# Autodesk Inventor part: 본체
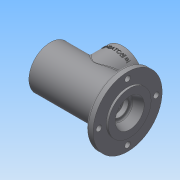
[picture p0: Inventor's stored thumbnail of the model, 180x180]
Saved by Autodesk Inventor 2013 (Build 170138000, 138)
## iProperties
Created: 2016-08
Part Number: 본체
Material: 일반
Document SubType Name: Modeling
Designer: Administrator
Density: 1 g/cm^3
Author: Administrator
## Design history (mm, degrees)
sketch "스케치1"
  geometry: L1 (-57.5, 0)-(57.5, 0); L2 (-57.5, 31)-(44.5, 31); L3 (44.5, 31)-(44.5, 50); L4 (44.5, 50)-(54.5, 50); L5 (57.5, 0)-(57.5, 21); L6 (57.5, 31)-(54.5, 31); L7 (54.5, 31)-(54.5, 50); L8 (-57.5, 20)-(-48.5, 20); L9 (-48.5, 20)-(-48.5, 24); L10 (-48.5, 24)-(-45.5, 24); L11 (-45.5, 24)-(-45.5, 20); L12 (-45.5, 20)-(-36.5, 20); L13 (-36.5, 20)-(-36.5, 17.5); L14 (-36.5, 17.5)-(-33.25, 17.5); L15 (-33.25, 17.5)-(-33.25, 18.5); L16 (-33.25, 18.5)-(-31.5, 18.5); L17 (-31.5, 18.5)-(-31.5, 17.5); L18 (-31.5, 17.5)-(-20.5, 17.5); L19 (17.5, 17.5)-(28.5, 17.5); L20 (28.5, 17.5)-(28.5, 16.5); L21 (28.5, 16.5)-(33.5, 16.5); L22 (33.5, 16.5)-(33.5, 10); L23 (33.5, 10)-(36.2, 10); L24 (36.2, 10)-(36.2, 12.5); L25 (36.2, 12.5)-(43.5, 12.5); L26 (43.5, 12.5)-(43.5, 16); L27 (43.5, 16)-(57.5, 21); L28 (-57.5, 31)-(-57.5, 20); L29 (57.5, 21)-(57.5, 31); L30 (-57.5, 20)-(-57.5, 0); L31 (17.5, 17.5)-(17.5, 24); L32 (17.5, 24)-(-20.5, 24); L33 (-20.5, 24)-(-20.5, 17.5); 2 further points
  constraints: 66 end point, 9 parallel, 9 perpendicular, 2 coincident, 1 horizontal, 1 midpoint
  dimensions: "d0" = 115 distance of L1.start L1.end; "d1" = 31 distance of L1.start L2.start; "d2" = 102 distance of L2.start L2.end; "d4" = 10 distance of L3.end L4.end; "d5" = 31 distance of L1.end L6.start; "d6" = 3 distance of L6.start L6.end; "d7" = 100 diameter of L4 L1; "d13" = 9 distance of L8.start L8.end; "d14" = 3 distance of L9.end L10.end; "d15" = 9 distance of L11.end L12.end; "d18" = 21 distance of L1.end L5.end; "d19" = 14 horizontal distance of L1.end L26.end; "d20" = 16 vertical distance of L1.end L26.end; "d21" = 10 horizontal distance of L22.end L25.end; "d22" = 2.7 distance between parallel lines of L24 L22; "d24" = 5 distance of L20.end L21.end; "d25" = 60 distance of L17.end L19.end; "d27" = 1.75 distance between parallel lines of L17 L15; "d28" = 40 diameter of L8 L1; "d29" = 48 diameter of L10 L1; "d30" = 40 diameter of L12 L1; "d31" = 35 diameter of L14 L1; "d32" = 37 diameter of L16 L1; "d33" = 35 diameter of L18 L1; "d34" = 35 diameter of L19 L1; "d35" = 33 diameter of L21 L1; "d36" = 20 diameter of L23 L1; "d37" = 25 diameter of L25 L1; "d38" = 1 distance of L16.end L17.end; "d92" = 38 distance of L31.end L32.end; "d93" = 11 distance from line of L32.end L17; "d97" = 24 distance from line of point (0, 0) L32
revolve "회전1" sketch "스케치1" stored, may be unused: angle "d41" = 90 deg
feature "스레드1" dims "d42" = 10, "d43" = 0
fillet "모깎기2" dims "d45" = 3
chamfer "모따기1" distance "d46" = 0.7; stored, may be unused: second distance "d47" = 2, angle "d48" = 30 deg
fillet "모깎기3" dims "d49" = 3
fillet "모깎기4" dims "d50" = 0.3
sketch "스케치3"
  geometry: C1 r 31 at (0, 0) reference; C2 r 50 at (0, 0) reference; A1 r 41.5 centre (0, 0) between (0, 41.5) and (-41.5, 0); 2 further points
  constraints: 4 point on circle, 2 horizontal alignment, 2 vertical alignment, 1 centre point, 1 coincident
  dimensions: "d51" = 83 diameter of A1
hole "구멍1" sketch "스케치3" at (0, 41.5), (-41.5, 0), (0, -41.5), (41.5, 0) diameter "d52" = 8; stored, may be unused: countersink angle "d56" = 90 deg, drill point angle "d58" = 118 deg; dims "d53" = 6, "d54" = 4, "d55" = 2, "d57" = 8
node "작업 평면1"
sketch "스케치4"
  geometry: L1 (57.5, 31)-(57.5, -31) reference; C1 r 30 at (1.5, 0); C2 r 19 at (1.5, 0); 1 further point
  constraints: 2 centre point, 1 coincident
  dimensions: "d60" = 60 diameter of C1; "d61" = 38 diameter of C2; "d62" = 56 distance from line of C1.centre L1; "d63" = 0 vertical distance of point (0, 0) C1.centre
fillet "모깎기10" dims "d98" = 3
extrude "돌출1" join sketch "스케치4" stored distance "d64" = 10; taper "d65" = 0 deg
extrude "돌출2" cut sketch "스케치4" distance "d66" = 50; taper "d67" = 0 deg
sketch "스케치5"
  geometry: C1 r 19 at (0, 0) reference; C2 r 30 at (0, 0) reference; A1 r 24 centre (0, 0) between (0, 24) and (-24, 0); 3 further points
  constraints: 4 point on circle, 2 horizontal alignment, 2 vertical alignment, 1 centre point, 1 coincident
  dimensions: "d68" = 48 diameter of A1
hole "구멍2" sketch "스케치5" at (0, 24), (-24, 0), (0, -24), (24, 0) diameter "d69" = 3.242; stored, may be unused: countersink angle "d73" = 90 deg, drill point angle "d75" = 118 deg; dims "d70" = 8, "d71" = 4, "d72" = 2, "d74" = 10
fillet "모깎기5" dims "d76" = 0.3
fillet "모깎기6" dims "d77" = 3
chamfer "모따기2" distance "d78" = 1; stored, may be unused: second distance "d79" = 2, angle "d80" = 30 deg
chamfer "모따기3" distance "d81" = 1; stored, may be unused: second distance "d82" = 2, angle "d83" = 30 deg
node "작업 평면2"
sketch "스케치7"
  geometry: L1 (-31.5, 49)-(28.5, 49) reference; L2 (-57.5, -31)-(-57.5, 31) reference; 2 further points
  constraints: 1 other
  dimensions: "d88" = 10 distance from line of point (-1.5, 39) L1; "d89" = 56 distance from line of L2 point (-1.5, 39)
feature "엠보싱1" sketch "스케치7" dims "d19" = 14, "d90" = 0.5, "d91" = 0
fillet "모깎기8" dims "d95" = 3
fillet "모깎기9" dims "d96" = 3
node "솔리드1"
other parameters: "d59" = 49, "d87" = 30.5
